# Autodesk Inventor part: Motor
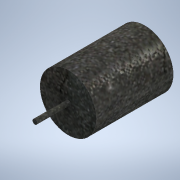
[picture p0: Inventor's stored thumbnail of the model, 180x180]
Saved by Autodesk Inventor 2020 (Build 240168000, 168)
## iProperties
Created: 2021-04
Part Number: Motor
Material: Acero
Document SubType Name: Modeling
Designer: Sergio
Density: 7.85 g/cm^3
Appearance: Placa
Mass: 194.709 g
Surface Area: 54.0708 cm^2
Volume: 24.8037 cm^3
Author: Sergio
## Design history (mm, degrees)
sketch "Boceto1"
  geometry: C1 r 13.85 at (0, 0); 1 further point
  constraints: 1 centre point, 1 coincident
  dimensions: "d14" = 27.7 diameter of C1
extrude "Extrusión1" new body sketch "Boceto1" distance "d4" = 37.8; taper "d5" = 0 deg
sketch "Boceto2"
  geometry: C1 r 1.15 at (0, 0); 1 further point
  constraints: 1 centre point, 1 coincident
  dimensions: "d6" = 2.3 diameter of C1
extrude "Extrusión2" join sketch "Boceto2" distance "d15" = 16.4; taper "d16" = 0 deg
node "Sólido1"
